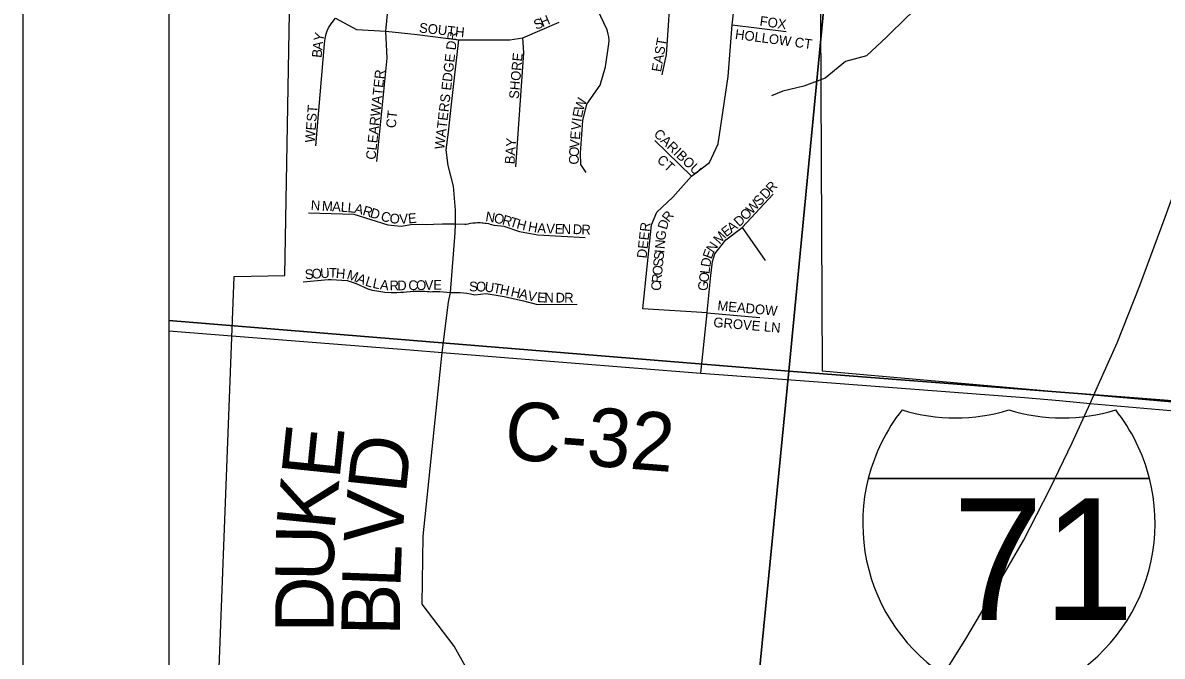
# Model space of a CAD drawing. Extents: x 0 to 34, y -4 to 22.
# Drawn here: x 2 to 2.78, y 15.235 to 15.668 of the extents above; entities that cross this region are included whole.
import ezdxf

# ---------------------------------------------------------------- set-up
doc = ezdxf.new("R2010")
doc.units = 0
for name, color, linetype in [('GM_X_City_Street', 7, 'Continuous'), ('GM_X_Corporation', 7, 'Continuous'), ('GM_X_County_Road', 7, 'Continuous'), ('GM_X_County_Road_Text', 7, 'Continuous'), ('GM_X_Interstate_Route', 7, 'Continuous'), ('GM_X_Interstate_Shield', 7, 'Continuous'), ('GM_X_Minor_River', 7, 'Continuous'), ('GM_X_Section', 7, 'Continuous'), ('GM_X_Township_Subdivision', 7, 'Continuous'), ('GM_X_Township_Subdivision_Text', 7, 'Continuous'), ('SH_Data', 7, 'Continuous'), ('SN_P_Text', 7, 'Continuous')]:
    doc.layers.add(name, color=color, linetype=linetype)

msp = doc.modelspace()

# ---------------------------------------------------------------- linework, layer by layer
at = {"layer": 'GM_X_City_Street'}
msp.add_line((2.1, 15.45744), (2.15739, 15.45292), dxfattribs=at)
at = {"layer": 'GM_X_Corporation'}
for points in [[(2.1, 18.31673), (2.1, 14.87547), (2.10462, 14.87567), (2.11825, 14.9007), (2.11921, 14.9021), (2.14326, 15.16102), (2.1318, 15.16159), (2.14466, 15.49475), (2.17937, 15.49536), (2.18562, 15.85514)], [(2.54504, 15.81673), (2.54698, 15.43021), (2.84819, 15.40349), (2.8664, 15.45657), (2.89517, 15.52919), (2.9177, 15.57945), (2.92048, 15.58689), (2.92234, 15.59897), (2.94851, 15.80105)]]:
    msp.add_lwpolyline(points, dxfattribs=at)
at = {"layer": 'GM_X_County_Road'}
for points in [[(2.15739, 15.45292), (2.26481, 15.44447)], [(2.26481, 15.44447), (2.28686, 15.44274), (2.37222, 15.43592)], [(2.31728, 15.20201), (2.29503, 15.24176), (2.2733, 15.27038), (2.27383, 15.31702), (2.28686, 15.44274)], [(2.37222, 15.43592), (2.46385, 15.4286), (2.54411, 15.42253)], [(2.54411, 15.42253), (2.68522, 15.41186), (2.70917, 15.40973), (2.7303, 15.40786), (2.85087, 15.39717)]]:
    msp.add_lwpolyline(points, dxfattribs=at)
at = {"layer": 'GM_X_Interstate_Route'}
for points in [[(2.73605, 15.42073), (2.74877, 15.44923), (2.76427, 15.48851), (2.78152, 15.53524), (2.79795, 15.58065), (2.81297, 15.62513), (2.83192, 15.68697), (2.84596, 15.73297), (2.8612, 15.78536), (2.86409, 15.79515)], [(2.22223, 14.61282), (2.24176, 14.63943), (2.26047, 14.6658), (2.2811, 14.69427), (2.30037, 14.72116), (2.31553, 14.74412), (2.33647, 14.77472), (2.35689, 14.8056), (2.39163, 14.85759), (2.42403, 14.90852), (2.44738, 14.94339), (2.48241, 14.99671), (2.51385, 15.04448), (2.54696, 15.09516), (2.57234, 15.13397), (2.59636, 15.17092), (2.62338, 15.21157), (2.64521, 15.2467), (2.66514, 15.28026), (2.68454, 15.31411), (2.7029, 15.34958), (2.71797, 15.38084), (2.7303, 15.40786), (2.73605, 15.42073)]]:
    msp.add_lwpolyline(points, dxfattribs=at)
at = {"layer": 'GM_X_Interstate_Shield'}
for p, q in [((2.57847, 15.35653), (2.77084, 15.35653)), ((2.77084, 15.35653), (2.57847, 15.35653)), ((2.77084, 15.35653), (2.57847, 15.35653))]:
    msp.add_line(p, q, dxfattribs=at)
for centre, start, end in [((2.69965, 15.32588), 141.66896, 165.80665), ((2.63812, 15.52295), 253.00908, 286.99093), ((2.71118, 15.52295), 253.00908, 286.99093), ((2.64965, 15.32588), 14.19335, 38.33104), ((2.69965, 15.32588), 165.80665, 258.46304), ((2.64965, 15.32588), 281.53696, 14.19335)]:
    msp.add_arc(centre, 0.125, start, end, dxfattribs=at)
at = {"layer": 'GM_X_Minor_River'}
msp.add_lwpolyline([(2.64555, 15.70113), (2.63217, 15.69766), (2.61853, 15.68456), (2.60516, 15.67227), (2.59125, 15.65864), (2.57734, 15.64554), (2.56289, 15.6418), (2.54899, 15.6303), (2.53427, 15.62496), (2.5201, 15.62149), (2.51234, 15.61828)], dxfattribs=at)
at = {"layer": 'GM_X_Section'}
for points in [[(2.1, 16.18581), (2.1, 15.4645), (2.52415, 15.42985), (2.59393, 16.1545)], [(3.26399, 15.68118), (3.30355, 16.09436), (2.59393, 16.1545), (2.52415, 15.42985), (3.22638, 15.37568), (3.22638, 15.68118)], [(2.1, 15.4645), (2.1, 14.72994), (2.45205, 14.69485), (2.52415, 15.42985)], [(3.22638, 15.37568), (2.52415, 15.42985), (2.45205, 14.69485), (3.15948, 14.56518), (3.22638, 15.2856)]]:
    msp.add_lwpolyline(points, close=True, dxfattribs=at)
at = {"layer": 'GM_X_Township_Subdivision'}
for points in [[(2.24836, 15.66242), (2.25067, 15.68623), (2.25265, 15.69614), (2.25629, 15.70805)], [(2.46819, 15.4697), (2.42419, 15.47257), (2.43014, 15.5301), (2.43377, 15.53869), (2.44468, 15.54894), (2.45757, 15.56332), (2.4698, 15.57258), (2.47575, 15.58547), (2.48269, 15.63143), (2.48533, 15.6668), (2.48765, 15.68664), (2.48665, 15.69193), (2.48566, 15.69854), (2.48486, 15.7064)], [(2.43741, 15.63258), (2.44038, 15.64663), (2.44187, 15.6663), (2.44402, 15.70317)], [(2.38552, 15.56572), (2.38188, 15.57126), (2.38155, 15.57894), (2.3832, 15.60142), (2.38585, 15.61266), (2.3951, 15.62556), (2.39874, 15.63812), (2.40105, 15.65386), (2.40108, 15.65644), (2.40087, 15.65864), (2.40053, 15.66052), (2.39998, 15.66251), (2.39947, 15.6639), (2.39345, 15.6768)], [(2.20043, 15.58407), (2.20651, 15.65373), (2.20679, 15.65743), (2.20753, 15.66067), (2.20823, 15.66264), (2.20923, 15.66479), (2.2105, 15.66691), (2.21163, 15.66844), (2.21398, 15.67135)], [(2.21398, 15.67135), (2.2282, 15.6637), (2.24836, 15.66242), (2.26984, 15.66027), (2.29826, 15.65663), (2.3171, 15.65663), (2.33329, 15.65663), (2.34222, 15.65796), (2.36701, 15.66854)], [(2.24227, 15.57336), (2.24934, 15.64391), (2.24836, 15.66242)], [(2.48533, 15.6668), (2.52235, 15.66217)], [(2.28686, 15.44274), (2.29118, 15.4771), (2.29264, 15.48365), (2.29586, 15.52448), (2.29595, 15.53067), (2.29611, 15.54014), (2.29459, 15.55639), (2.29099, 15.57068), (2.28967, 15.58126), (2.29132, 15.59349), (2.2933, 15.61266), (2.29826, 15.65663)], [(2.33726, 15.56969), (2.34288, 15.64771), (2.34222, 15.65796)], [(2.45757, 15.56332), (2.43241, 15.58762)], [(2.46825, 15.47025), (2.47079, 15.49538), (2.47178, 15.50497), (2.47343, 15.51026), (2.48104, 15.51985), (2.49227, 15.52812), (2.51343, 15.55092)], [(2.19547, 15.53828), (2.22654, 15.53726), (2.24968, 15.53001), (2.25893, 15.52902), (2.26686, 15.53035), (2.276, 15.53016), (2.28094, 15.53043), (2.28715, 15.53067), (2.29595, 15.53067)], [(2.29595, 15.53067), (2.30241, 15.53038), (2.30336, 15.53044), (2.30471, 15.53076), (2.30633, 15.53107), (2.30786, 15.53128), (2.30971, 15.53145), (2.31105, 15.53151), (2.3129, 15.5315), (2.31419, 15.53143), (2.31501, 15.53136), (2.31601, 15.53125), (2.31694, 15.53112), (2.31855, 15.53082), (2.31968, 15.53057), (2.32075, 15.53029), (2.32227, 15.52983), (2.32244, 15.52979), (2.32267, 15.52974), (2.32909, 15.52899), (2.33991, 15.52539), (2.35247, 15.52307), (2.38486, 15.52142)], [(2.49227, 15.52812), (2.50781, 15.50564)], [(2.19184, 15.49092), (2.20904, 15.49266), (2.21093, 15.49254), (2.22191, 15.49192), (2.22819, 15.48994), (2.23599, 15.48618), (2.23913, 15.48538), (2.24211, 15.48477), (2.24506, 15.48431), (2.24776, 15.484), (2.25213, 15.48373), (2.25586, 15.48373), (2.25863, 15.48386), (2.26041, 15.48401), (2.2625, 15.48425), (2.26497, 15.48443), (2.26708, 15.48454), (2.27087, 15.4846), (2.27479, 15.48451), (2.27662, 15.48441), (2.27808, 15.48431), (2.2789, 15.48425), (2.2804, 15.48428), (2.28543, 15.48437), (2.29264, 15.48365)], [(2.29264, 15.48365), (2.29919, 15.48362), (2.30141, 15.48342), (2.30391, 15.48315), (2.3063, 15.48271), (2.30934, 15.48203), (2.3171, 15.48299), (2.32933, 15.48101), (2.34255, 15.47803), (2.35213, 15.47539), (2.37924, 15.47572)], [(2.46385, 15.4286), (2.46819, 15.4697), (2.46825, 15.47025)], [(2.46819, 15.4697), (2.50417, 15.46662)]]:
    msp.add_lwpolyline(points, dxfattribs=at)
at = {"layer": 'SH_Data'}
for p, q in [((2, 21), (2, 14)), ((2.1, 20.9), (2.1, 14.1))]:
    msp.add_line(p, q, dxfattribs=at)
at = {"layer": 'SN_P_Text'}
msp.add_lwpolyline([(8.9, 14.1), (8.9, 20.9), (2.1, 20.9), (2.1, 14.1)], close=True, dxfattribs=at)

# ---------------------------------------------------------------- texts
at = {"layer": 'GM_X_County_Road_Text'}
for s, rotation, p in [('C-32', 355.52327, (2.32867, 15.36993)), ('E', 84.09238, (2.21664, 15.35524)), ('D', 83.89031, (2.262, 15.34554)), ('K', 84.29339, (2.21315, 15.32025)), ('V', 85.69376, (2.25938, 15.31077)), ('U', 89.27504, (2.21275, 15.28597)), ('L', 87.85669, (2.25829, 15.28127)), ('D', 89.99271, (2.21275, 15.2509)), ('B', 89.38721, (2.25794, 15.2487))]:
    msp.add_text(s, height=0.04, rotation=rotation, dxfattribs=at).set_placement(p)
at = {"layer": 'GM_X_Interstate_Shield'}
msp.add_text('71', height=0.083333, dxfattribs=at).set_placement((2.63615, 15.25966))
at = {"layer": 'GM_X_Township_Subdivision_Text'}
for s, height, rotation, p in [('S', 0.00667, 22.87209, (2.3512, 15.66331)), ('H', 0.00667, 22.88907, (2.35553, 15.66514)), ('FOX', 0.006667, 351.86662, (2.50382, 15.66633)), ('Y', 0.00667, 78.60434, (2.20543, 15.65498)), ('SOUTH', 0.006667, 353.79492, (2.27087, 15.66164)), ('WATERS EDGE DR', 0.0066667, 83.40071, (2.28826, 15.58132)), ('HOLLOW CT', 0.006667, 352.26807, (2.48701, 15.65731)), ('A', 0.00667, 84.37211, (2.20488, 15.64931)), ('EAST', 0.006667, 80.2705, (2.4367, 15.63424)), ('B', 0.00667, 84.35706, (2.20436, 15.64406)), ('SHORE', 0.006667, 85.02799, (2.3393, 15.61592)), ('CLEARWATER', 0.006667, 83.99182, (2.24132, 15.57429)), ('W', 0.00667, 71.04399, (2.38337, 15.60742)), ('WEST', 0.006667, 85.48871, (2.19967, 15.58599)), ('CT', 0.006667, 83.66379, (2.25507, 15.59591)), ('E', 0.00667, 78.78115, (2.38251, 15.60305)), ('V', 0.00667, 84.87878, (2.3816, 15.59449)), ('I', 0.00667, 81.79569, (2.38211, 15.60024)), ('E', 0.00667, 85.43152, (2.38109, 15.58807)), ('CARIBOU', 0.006667, 316.27228, (2.43117, 15.59149)), ('BAY', 0.006667, 86.04937, (2.33636, 15.57131)), ('O', 0.00667, 87.42025, (2.38037, 15.57642)), ('V', 0.00667, 85.5376, (2.38063, 15.58222)), ('C', 0.00667, 89.85426, (2.38036, 15.57122)), ('CT', 0.006667, 317.2983, (2.43335, 15.57369)), ('D', 0.00667, 46.74694, (2.50842, 15.54715)), ('R', 0.00667, 46.73466, (2.51244, 15.55142)), ('N', 0.00667, 356.56681, (2.19688, 15.54021)), ('M', 0.00667, 356.56017, (2.2045, 15.53975)), ('A', 0.00667, 356.56681, (2.21153, 15.53933)), ('L', 0.00667, 356.55491, (2.21739, 15.53897)), ('L', 0.00667, 354.55578, (2.22201, 15.5387)), ('A', 0.00667, 345.73585, (2.22641, 15.5383)), ('W', 0.00667, 46.74108, (2.49877, 15.53689)), ('S', 0.00667, 46.73268, (2.504, 15.54245)), ('R', 0.00667, 343.32402, (2.23203, 15.53687)), ('D', 0.00667, 343.30704, (2.23709, 15.53536)), ('C', 0.00667, 343.30996, (2.24439, 15.53317)), ('O', 0.00667, 352.64343, (2.25061, 15.5314)), ('V', 0.00667, 3.34216, (2.25779, 15.5306)), ('E', 0.00667, 4.89429, (2.26384, 15.53096)), ('N', 0.00667, 350.33644, (2.3162, 15.53261)), ('O', 0.00667, 348.27004, (2.32192, 15.53163)), ('R', 0.00667, 344.71507, (2.32756, 15.53047)), ('R', 0.00667, 51.78004, (2.44192, 15.53133)), ('O', 0.00667, 46.68885, (2.49474, 15.53262)), ('T', 0.00667, 343.23272, (2.3326, 15.52909)), ('H', 0.00667, 345.3171, (2.33735, 15.52766)), ('H', 0.00667, 350.03471, (2.34534, 15.52572)), ('A', 0.00667, 356.15317, (2.35189, 15.52461)), ('V', 0.00667, 358.31514, (2.35802, 15.5242)), ('E', 0.00667, 358.34787, (2.36389, 15.52403)), ('N', 0.00667, 358.33845, (2.36858, 15.5239)), ('D', 0.00667, 358.33765, (2.3762, 15.52368)), ('R', 0.00667, 358.34276, (2.38207, 15.52351)), ('DEER', 0.006667, 83.65713, (2.42671, 15.50683)), ('D', 0.00667, 72.5534, (2.44046, 15.52629)), ('E', 0.00667, 38.12654, (2.48121, 15.52138)), ('A', 0.00667, 37.11026, (2.48488, 15.52426)), ('D', 0.00667, 43.16799, (2.49015, 15.52829)), ('G', 0.00667, 83.58257, (2.43955, 15.51907)), ('M', 0.00667, 48.2984, (2.47676, 15.51634)), ('N', 0.00667, 84.63737, (2.43901, 15.51326)), ('E', 0.00667, 69.80212, (2.47117, 15.5062)), ('N', 0.00667, 56.38874, (2.4726, 15.51024)), ('S', 0.00667, 84.75742, (2.43788, 15.50099)), ('S', 0.00667, 84.75742, (2.43831, 15.50567)), ('I', 0.00667, 84.70265, (2.43874, 15.51034)), ('D', 0.00667, 80.67061, (2.4703, 15.50074)), ('S', 0.00667, 4.18292, (2.1932, 15.49269)), ('O', 0.00667, 4.20239, (2.19788, 15.49303)), ('U', 0.00667, 3.78355, (2.20372, 15.49346)), ('T', 0.00667, 358.16913, (2.2094, 15.49384)), ('H', 0.00667, 355.2291, (2.214, 15.4937)), ('M', 0.00667, 342.17554, (2.2212, 15.4931)), ('O', 0.00667, 84.74497, (2.43734, 15.49515)), ('L', 0.00667, 83.18001, (2.46976, 15.49615)), ('A', 0.00667, 337.67098, (2.22778, 15.49099)), ('L', 0.00667, 342.72224, (2.23381, 15.48854)), ('L', 0.00667, 348.00482, (2.23894, 15.48698)), ('A', 0.00667, 352.78005, (2.24413, 15.4859)), ('R', 0.00667, 0.81331, (2.25097, 15.48511)), ('D', 0.00667, 0.80878, (2.25624, 15.48518)), ('C', 0.00667, 0.78957, (2.26387, 15.48529)), ('O', 0.00667, 0.80365, (2.26915, 15.48536)), ('V', 0.00667, 0.80365, (2.27501, 15.48545)), ('E', 0.00667, 0.81154, (2.28088, 15.48553)), ('S', 0.00667, 359.80874, (2.30534, 15.48448)), ('O', 0.00667, 359.25679, (2.31001, 15.48446)), ('U', 0.00667, 352.63643, (2.31568, 15.4844)), ('T', 0.00667, 349.31154, (2.3214, 15.48366)), ('C', 0.00667, 84.74618, (2.43637, 15.48463)), ('R', 0.00667, 84.722, (2.43685, 15.48989)), ('G', 0.00667, 83.16503, (2.46836, 15.4845)), ('O', 0.00667, 83.17545, (2.46906, 15.49033)), ('H', 0.00667, 348.40288, (2.32598, 15.4828)), ('H', 0.00667, 347.10369, (2.3334, 15.48124)), ('A', 0.00667, 347.15842, (2.33913, 15.47993)), ('V', 0.00667, 347.68396, (2.34491, 15.47861)), ('E', 0.00667, 355.93655, (2.35168, 15.47721)), ('N', 0.00667, 359.90283, (2.35687, 15.47686)), ('D', 0.00667, 359.99285, (2.3645, 15.47685)), ('R', 0.00667, 359.99406, (2.37037, 15.47685)), ('MEADOW', 0.006667, 354.64365, (2.47501, 15.47156)), ('GROVE LN', 0.006667, 355.10046, (2.47226, 15.46014))]:
    msp.add_text(s, height=height, rotation=rotation, dxfattribs=at).set_placement(p)

doc.saveas('drawing.dxf')
